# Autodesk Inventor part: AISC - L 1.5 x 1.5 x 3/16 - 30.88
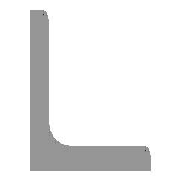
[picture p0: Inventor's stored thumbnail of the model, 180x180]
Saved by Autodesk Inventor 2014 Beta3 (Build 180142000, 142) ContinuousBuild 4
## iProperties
_CCFamilyMember: 5
_CCFamilyDisplayName: ANSI L (Equal angles) - Angle Steel
_FrameMemberDoc: Frame Member File
_Version: 15.0.0
_GetPNFromCC: 1
Created: 2010-11
Part Number: AISC - L 1.5 x 1.5 x 3/16 - 30.88
Material: Steel, Mild
Description: Angle Steel
Document SubType Name: Modeling
Standard: ANSI
Designer: Beta-8540w
Standards Organization: ANSI
Language: en-US
Size Designation: L 1.5 x 1.5 x 3/16
Categories: <MemberInstance><Categories><Category DisplayName="Structural Shapes" InternalName="089c4875-fa83-4c05-b084-43b9cc11f5ed" Mnemonic="GRDR"><CategoryParameter Dis
Stock Number: L 1.5 x 1.5 x 3/16
Density: 7.86 g/cm^3
Appearance: Steel
IsCustomPart: 1
G_L: 30.880 in
G_W: 1.500 in
G_H: 1.500 in
+D492D07F-02B9-496C-B776-82EB711B3C50+CUTDETAIL1: Cut
Author: Beta-8540w
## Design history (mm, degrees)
node "Start plane"
node "End plane"
sketch "Sketch"
  geometry: L1 (38.1, 0)-(0, 0); L2 (0, 0)-(0, 38.1); L3 (0, 38.1)-(2.476, 38.1); L4 (4.762, 35.814)-(4.762, 9.589); L5 (9.588, 4.763)-(35.814, 4.763); L6 (38.1, 2.477)-(38.1, 0); L7 (0, -11.041)-(0, 31.538); L8 (-11.041, 0)-(31.538, 0); L9 (0, 48.496)-(0, -20.964) reference; L10 (-20.964, 0)-(48.496, 0) reference; A1 r 4.826 centre (9.588, 9.589) between (4.762, 9.589) and (9.588, 4.763); A2 r 2.286 centre (2.476, 35.814) between (4.762, 35.814) and (2.476, 38.1); A3 r 2.286 centre (35.814, 2.477) between (38.1, 2.477) and (35.814, 4.763); 3 further points
  constraints: 16 end point, 6 point on circle, 6 point on line, 6 tangent, 4 parallel, 3 centre point, 2 collinear, 1 equal radius, 1 horizontal, 1 perpendicular
  dimensions: "d0" = 38.1 distance between parallel lines of L6 L2 (= G_H); "d1" = 38.1 distance between parallel lines of L3 L1 (= G_H); "d2" = 4.7625 distance between parallel lines of L2 L4 (= G_T); "d3" = 4.7625 distance between parallel lines of L1 L5 (= G_T); "d10" = 0 distance between parallel lines of L7 L2 (computed from ex); "d11" = 0 distance between parallel lines of L8 L1 (computed from d10); "d14" = 4.826 radius of A1 (= G_IR); "d15" = 2.286 radius of A2 (= G_ER)
extrude "Body" new body sketch "Sketch" stored distance "d4" = 784.34465 (= G_L); taper "d5" = 0 deg
node "Driven Length"
  sketch "Sketch3"
    geometry: L1 (0, 0)-(10, 0) reference
    constraints: 2 end point, 1 horizontal
  workplane "Work Plane3"
  sketch "Sketch4"
    geometry: L1 (-2, 0)-(12, 0) reference; L2 (-2, 784.345)-(12, 784.345) reference
    dimensions: "d17" = 784.34465 distance between parallel lines of L1 L2 (derived)
workplane "Work Plane4"
split "Split1"
body "Solid1"
other parameters: "G_H" = 38.1 [user parameter; used in 2 equation terms], "G_T" = 4.7625 [user parameter; used in 2 equation terms], "G_ER" = 2.286 [user parameter; used in 1 equation term], "G_IR" = 4.826 [user parameter; used in 1 equation term], "G_L" = 784.34465 (= d17) [user parameter; used in 1 equation term], "ex" = 0 [user parameter; used in 1 equation term], "G_OFFSET_START" = 0 [user parameter; used in 1 equation term], "G_OFFSET_END" = -32.98927 [user parameter; used in 1 equation term], "d12" = 0 (computed from G_OFFSET_START), "d13" = 784.34465 (= G_OFFSET_END + B_L), "B_L" = 817.33392 [user parameter; used in 1 equation term], "d16" = 90 deg, "MAS" = 0.26787 [user parameter]
